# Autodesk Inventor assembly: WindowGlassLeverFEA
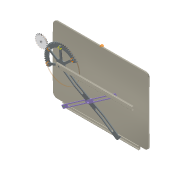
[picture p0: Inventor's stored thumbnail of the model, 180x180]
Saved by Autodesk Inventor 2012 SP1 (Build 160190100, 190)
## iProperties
Created: 2006-09
Part Number: WindowGlassLeverFEA
Document SubType Name: Assembly
Designer: Maxime Debono
Author: Maxime Debono
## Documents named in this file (8)
- C:\Users\jhh70193\Documents\IGI Inventor Dyn Sim 2012\Dataset\WindowGlassLeverFEA.iam
- C:\Users\jhh70193\Documents\IGI Inventor Dyn Sim 2012\Dataset\Sub-Assemblies\Ground_asm.iam
- C:\Users\jhh70193\Documents\IGI Inventor Dyn Sim 2012\Dataset\Sub-Assemblies\Main Arm asm.iam
- C:\Users\jhh70193\Documents\IGI Inventor Dyn Sim 2012\Dataset\Parts\Spur Gear12.ipt
- C:\Users\jhh70193\Documents\IGI Inventor Dyn Sim 2012\Dataset\Parts\Pin.ipt
- C:\Users\jhh70193\Documents\IGI Inventor Dyn Sim 2012\Dataset\Sub-Assemblies\Upper_Pin_asm.iam
- C:\Users\jhh70193\Documents\IGI Inventor Dyn Sim 2012\Dataset\Sub-Assemblies\Window Glass Asm.iam
- C:\Users\jhh70193\Documents\IGI Inventor Dyn Sim 2012\Dataset\Parts\Second Arm.ipt
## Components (7 placed, 7 different names)
1. Ground_asm:1 [sub-assembly]
2. Main Arm asm:1 [sub-assembly]
3. Second Arm:1
4. Spur Gear1:1
5. Pin:1
6. Upper_Pin_asm:1 [sub-assembly]
7. Window Glass Asm:1 [sub-assembly]
